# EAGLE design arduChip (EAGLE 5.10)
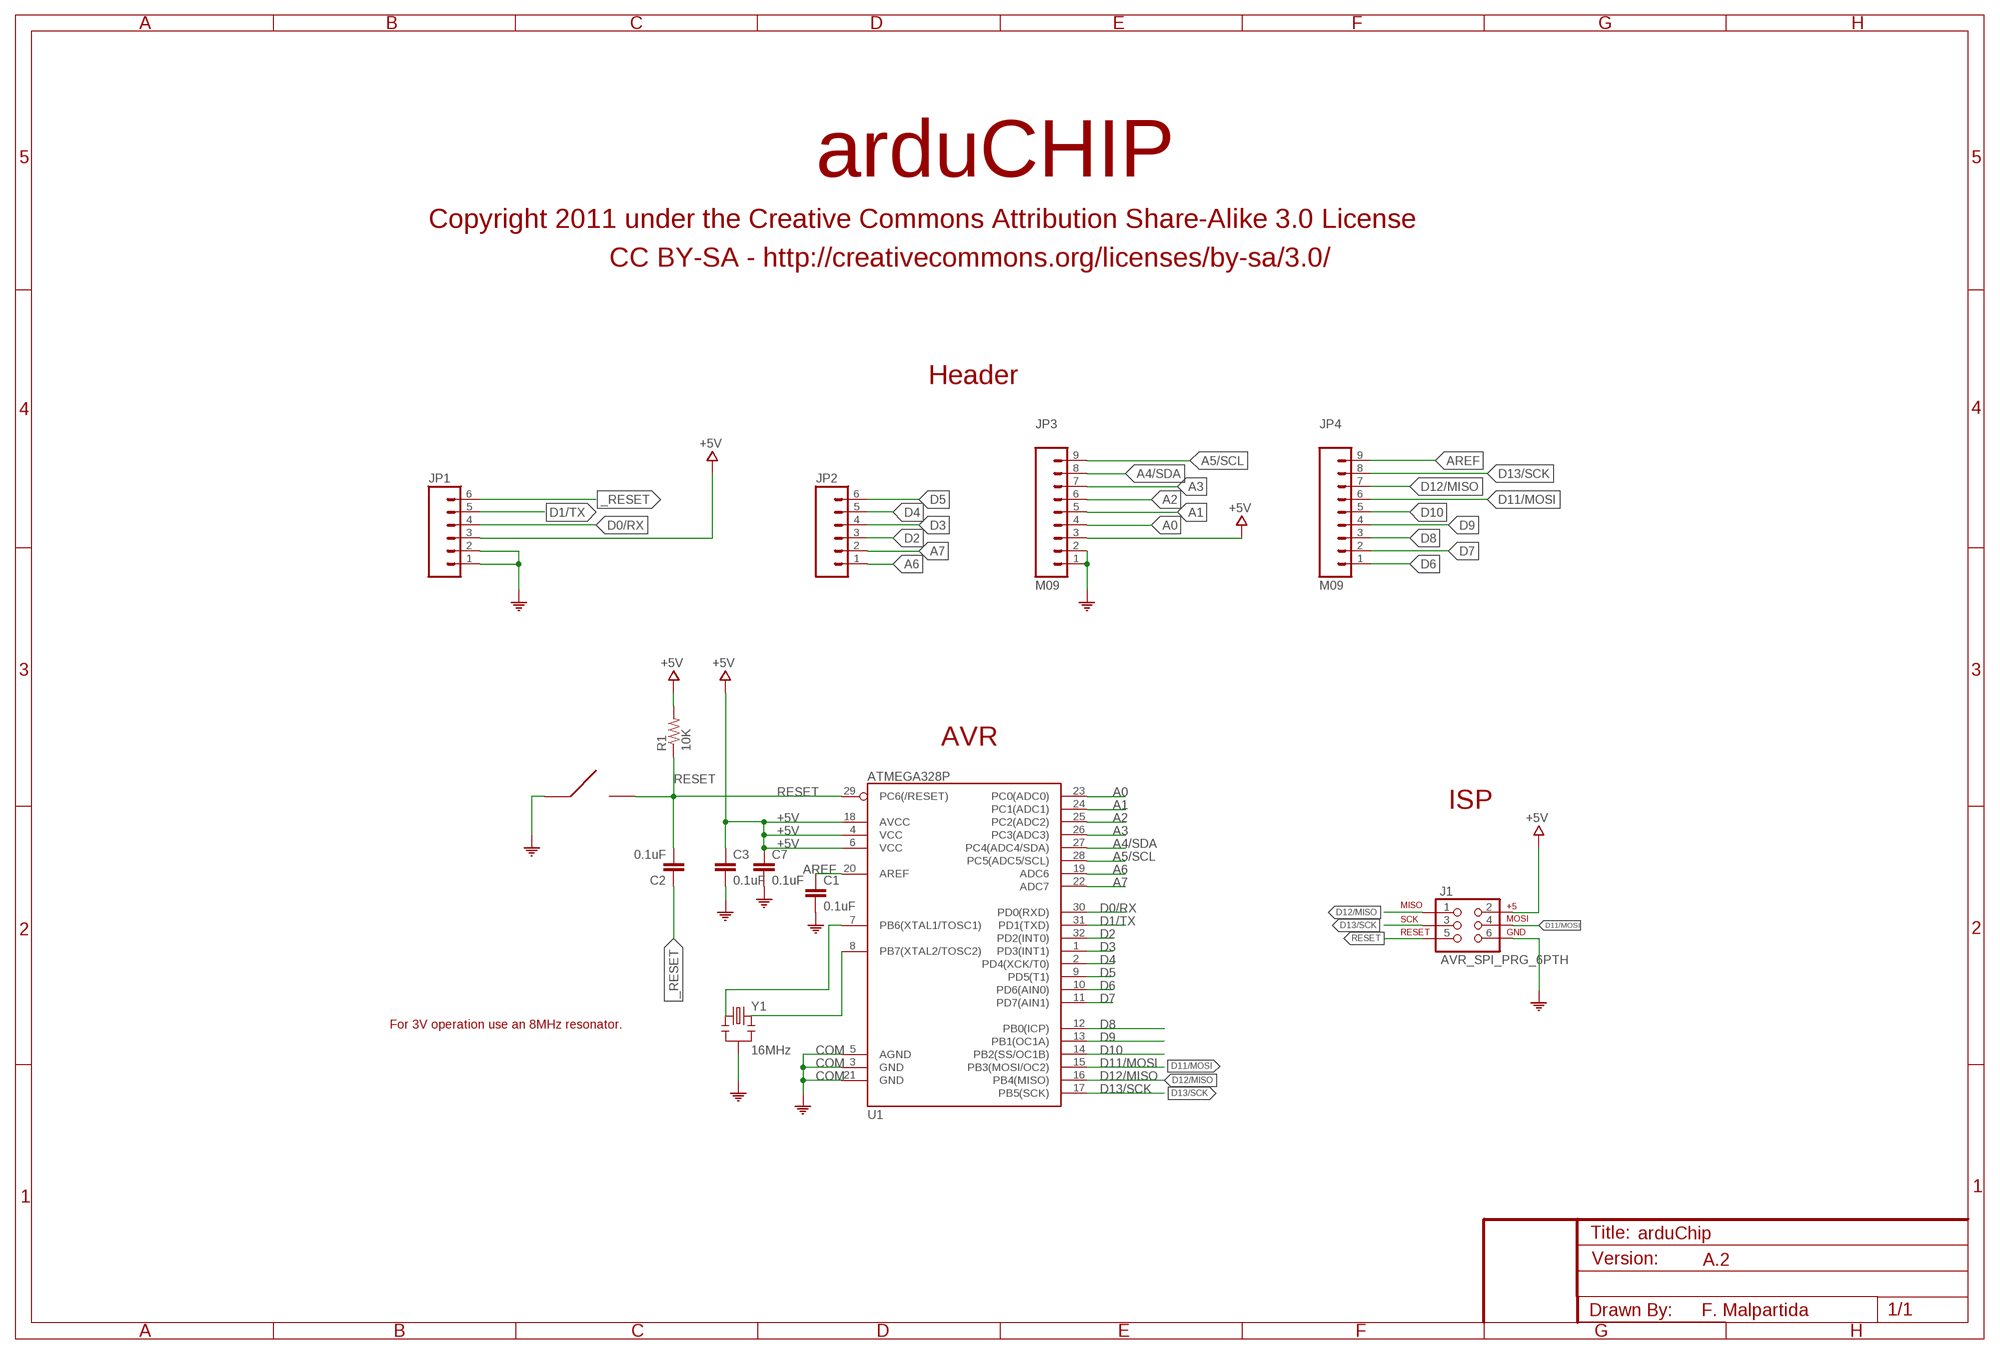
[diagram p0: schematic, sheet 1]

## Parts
C1  0.1uF  CAP0805  [0805]
C2  0.1uF  CAP0805  [0805]
C3  0.1uF  CAP0805  [0805]
C7  0.1uF  CAP0805  [0805]
J1  AVR_SPI_PRG_6PTH  [2X3]
JP1  M06SIP  [1X06]
JP2  M06SIP  [1X06]
JP3  M09  [1X09]
JP4  M09  [1X09]
R1  10K  RESISTOR0805-RES  [0805]
SW1  B3U-1000P  B3U-SWITCH_  [B3U_1000P]
U1  ATMEGA328P  ATMEGA168  [TQFP32-08]
Y1  16MHz  RESONATORSMD  [RESONATOR-SMD]

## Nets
+5V: C3.1 C7.1 J1.2 JP1.3 JP3.3 R1.2 U1.4(VCC) U1.6(VCC) U1.18(AVCC)
_RESET: C2.1 JP1.6
A0: JP3.4 U1.23(PC0(ADC0))
A1: JP3.5 U1.24(PC1(ADC1))
A2: JP3.6 U1.25(PC2(ADC2))
A3: JP3.7 U1.26(PC3(ADC3))
A4/SDA: JP3.8 U1.27(PC4(ADC4/SDA))
A5/SCL: JP3.9 U1.28(PC5(ADC5/SCL))
A6: JP2.1 U1.19(ADC6)
A7: JP2.2 U1.22(ADC7)
AREF: C1.1 JP4.9 U1.20(AREF)
COM: C1.2 C3.2 C7.2 J1.6 JP1.1 JP1.2 JP3.1 JP3.2 SW1.P$1 U1.3(GND) U1.5(AGND) U1.21(GND) Y1.2
D0/RX: JP1.4 U1.30(PD0(RXD))
D1/TX: JP1.5 U1.31(PD1(TXD))
D2: JP2.3 U1.32(PD2(INT0))
D3: JP2.4 U1.1(PD3(INT1))
D4: JP2.5 U1.2(PD4(XCK/T0))
D5: JP2.6 U1.9(PD5(T1))
D6: JP4.1 U1.10(PD6(AIN0))
D7: JP4.2 U1.11(PD7(AIN1))
D8: JP4.3 U1.12(PB0(ICP))
D9: JP4.4 U1.13(PB1(OC1A))
D10: JP4.5 U1.14(PB2(SS/OC1B))
D11/MOSI: J1.4 JP4.6 U1.15(PB3(MOSI/OC2))
D12/MISO: J1.1 JP4.7 U1.16(PB4(MISO))
D13/SCK: J1.3 JP4.8 U1.17(PB5(SCK))
N$1: U1.8(PB7(XTAL2/TOSC2)) Y1.3
N$2: U1.7(PB6(XTAL1/TOSC1)) Y1.1
RESET: C2.2 J1.5 R1.1 SW1.P$2 U1.29(PC6(/RESET))

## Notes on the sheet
- arduCHIP
- Copyright 2011 under the Creative Commons Attribution Share-Alike 3.0 License
- CC BY-SA - http://creativecommons.org/licenses/by-sa/3.0/
- Header
- AVR
- ISP
- For 3V operation use an 8MHz resonator.
- A.2
- F. Malpartida

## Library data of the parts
C1-C3 C7 = SparkFun:CAP: Capacitor
J1 = SparkFun:AVR_SPI_PRG_6: AVR ISP 6 Pin This is the reduced ISP connector for AVR programming. Common on Arduino. This footprint will take up less PCB space and can be used with a 10-pin to 6-pin adapter such as SKU: BOB-08508
JP1 JP2 = sparkfun_2:M06: Header 6 Standard 6-pin 0.1" header. Use with straight break away headers (SKU : PRT-00116), right angle break away headers (PRT-00553), swiss pins (PRT-00743), machine pins (PRT-00117), and female headers (PRT-00115). Molex polarized connector foot print use with SKU : PRT-08094 with associated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
JP3 JP4 = sparkfun_2:M09: Header 9 Standard 9-pin 0.1" header. Use with straight break away headers (SKU : PRT-00116), right angle break away headers (PRT-00553), swiss pins (PRT-00743), machine pins (PRT-00117), and female headers (PRT-00115).
R1 = SparkFun:RESISTOR: Resistor
SW1 = fmc:B3U-SWITCH
U1 = SparkFun:ATMEGA168
Y1 = SparkFun:RESONATOR: Resonator Small SMD resonator. This is the itty bitty 10/20MHz resonators with built in caps. CSTCE10M0G55 and CSTCE20M0V53. Footprint has been reviewed closely but hasn't been tested yet.

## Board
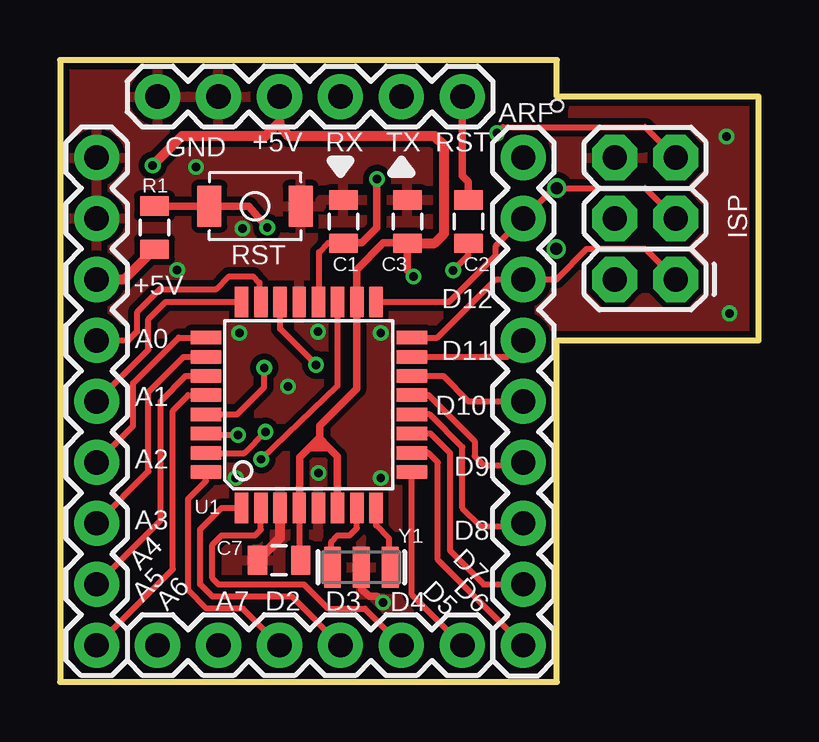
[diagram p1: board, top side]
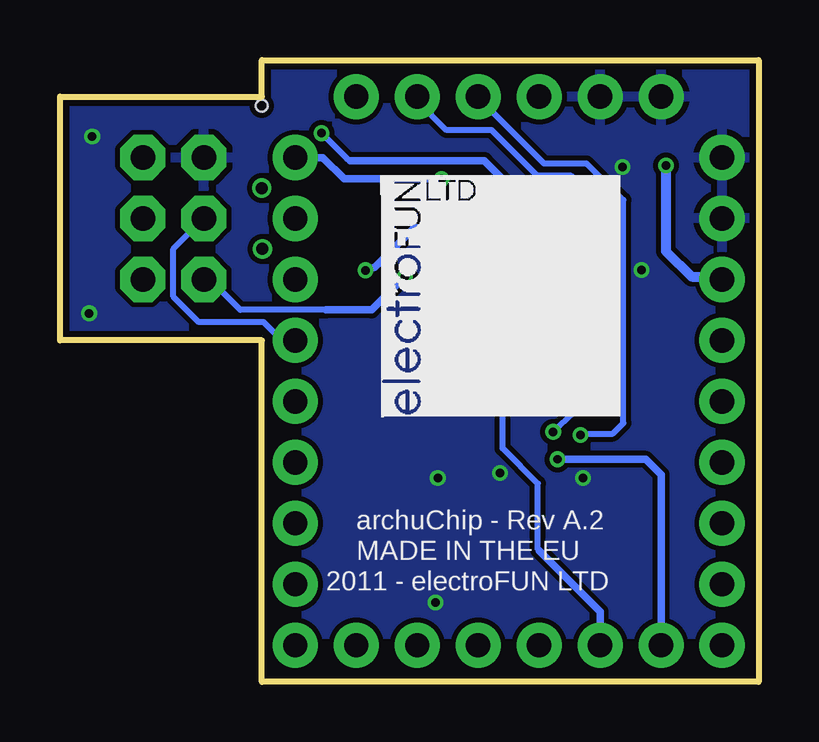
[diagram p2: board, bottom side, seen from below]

Size 29.11 x 25.91 mm. Coordinates in mm from the lower left corner, seen from the top.
Outline: 0,0 20.7,0 20.7,14.22 29.11,14.22 29.11,24.38 20.7,24.38 20.7,25.91 0,25.91 0,0
Copper layers (1*16): Top 0.0356mm / dielectric 1.5011mm / Bottom 0.0356mm
Design rules "SparkFun_itead_fmc *": minimum track width 8mil, minimum drill 0.35mm, track to track 8mil, track to pad 8mil, pad to pad 8mil, via to via 8mil, smd to smd 8mil, copper to edge 10mil, drill to drill 8mil, minimum pad ring 12mil, minimum via ring 6mil, stop-mask expansion 4mil, vias tented up to drill 25mil, thermal gap 10mil
Holes 0.5 mm at 20.7,24

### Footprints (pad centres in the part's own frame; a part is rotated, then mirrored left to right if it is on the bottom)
0805 = smd 0.8 x 1.2: 1 -0.9,0; 2 0.9,0
2X3 = drill 1.016 pad 1.88 octagon: 1 0,0; 2 0,2.54; 3 2.54,0; 4 2.54,2.54; 5 5.08,0; 6 5.08,2.54
1X06 = drill 1.016 pad 1.88 round: 1 0,0; 2 2.54,0; 3 5.08,0; 4 7.62,0; 5 10.16,0; 6 12.7,0
1X09 = drill 1.016 pad 1.88 round: 1 0,0; 2 2.54,0; 3 5.08,0; 4 7.62,0; 5 10.16,0; 6 12.7,0; 7 15.24,0; 8 17.78,0; 9 20.32,0
B3U_1000P = smd 1 x 1.7: P$1 -1.9,0; P$2 1.9,0
TQFP32-08 = smd 1.27 x 0.559: 1 -4.293,2.8; 2 -4.293,2; 3 -4.293,1.2; 4 -4.293,0.4; 5 -4.293,-0.4; 6 -4.293,-1.2; 7 -4.293,-2; 8 -4.293,-2.8; 17 4.293,-2.8; 18 4.293,-2; 19 4.293,-1.2; 20 4.293,-0.4; 21 4.293,0.4; 22 4.293,1.2; 23 4.293,2; 24 4.293,2.8 | smd 0.559 x 1.27: 9 -2.8,-4.293; 10 -2,-4.293; 11 -1.2,-4.293; 12 -0.4,-4.293; 13 0.4,-4.293; 14 1.2,-4.293; 15 2,-4.293; 16 2.8,-4.293; 25 2.8,4.293; 26 2,4.293; 27 1.2,4.293; 28 0.4,4.293; 29 -0.4,4.293; 30 -1.2,4.293; 31 -2,4.293; 32 -2.8,4.293
RESONATOR-SMD = smd 0.7 x 1.7: 1 -1.2,0; 2 0,0; 3 1.2,0

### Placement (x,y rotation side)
C1  11.81,19.18 90 top
C2  17.02,19.18 270 top
C3  14.48,19.18 90 top
C7  9.13,5.06 180 top
J1  25.65,16.76 90 top
JP1  4.06,24.38 0 top
JP2  4.06,1.52 0 top
JP3  1.52,21.84 270 top
JP4  19.3,1.52 90 top
R1  3.94,18.92 270 top
SW1  8.13,19.81 180 top
U1  10.37,11.54 90 top
U$36  [ELECTROFUN]  15.75,11.05 0 bottom
Y1  12.56,4.77 0 top

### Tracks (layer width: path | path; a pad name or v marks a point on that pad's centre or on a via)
+5V  (via drill 0.35, 0.35 pad 0.25)
  Top 0.254: U1.18 12.4,15.87 | 9.98,5.18 9.98,7.13 U1.4 | 11.56,7.26 U1.6 | JP1.3 9.14,23.32
  Top 0.305: 9.14,23.24 JP1.3 | 9.98,7.13 9.98,9.35 10.39,9.75 | 10.39,9.75 10.41,9.78 | 10.41,9.78 10.82,9.78 | 11.18,9.78 11.56,9.4 11.56,7.26 | C7.1 10.03,5.21 9.98,5.18 | 12.37,15.81 12.37,17.17 13.46,18.29 14.47,18.29 C3.1 14.48,17.14 v14.73,16.89 | U1.18 12.37,12.21 10.82,10.67 10.82,9.78 | 11.18,9.78 10.82,9.78 | 10.41,9.78 10.79,10.16 11.18,9.78 | 10.39,9.75 11.18,9.75 11.18,9.78
  Top 0.406: C3.1 15.61,18.28 16,18.67 16,22.35 15.62,22.73 9.52,22.73 9.14,23.24 | U1.18 12.37,15.81 | JP3.3 2.68,16.76 R1.2 | 9.14,23.32 8.56,22.73 5.08,22.73 v3.86,21.51
  Bottom 0.254: J1.2 22.86,16.76 21.59,15.49 18.03,15.49
  Bottom 0.305: v14.73,16.89 16.13,15.49 18.03,15.49
  Bottom 0.406: v3.86,21.51 3.86,17.95 2.79,16.88 1.7,16.88 JP3.3
_RESET
  Top 0.305: JP1.6 16.76,21.08 17.02,20.83 C2.1
A0
  Top 0.254: JP3.4 2.84,14.22 3.23,14.61 3.23,15.42 4.17,16.36 6.5,16.36 7.04,16.89 8.05,16.89 8.31,16.64 8.31,15.9 U1.23
A1
  Top 0.254: U1.24 4.4,15.83 3.68,15.11 3.68,13.84 JP3.5
A2
  Top 0.254: U1.25 4.94,14.34 3.05,12.45 3.05,10.67 JP3.6
A3
  Top 0.254: U1.26 5.16,13.54 3.68,12.06 3.68,8.76 JP3.7
A4/SDA
  Top 0.254: U1.27 5.25,12.74 4.19,11.68 4.19,6.73 JP3.8
A5/SCL
  Top 0.254: U1.28 5.34,11.94 4.7,11.3 4.7,4.7 JP3.9
A6  (via drill 0.35)
  Top 0.254: U1.19 11.57,12.33 v8.38,9.27
  Bottom 0.305: v8.38,9.27 4.7,9.27 4.06,8.64 JP2.1
A7  (via drill 0.35)
  Top 0.254: U1.22 9.17,14.71 v10.67,13.21
  Bottom 0.254: v10.67,13.21 10.67,9.73 9.19,8.26 9.19,5.51 9.14,5.46
  Bottom 0.305: 9.14,5.46 6.6,2.92 JP2.2
AREF  (via drill 0.35)
  Top 0.254: C1.1 11.16,18.28 10.79,17.91 10.79,15.86 U1.20
  Top 0.305: v13.21,20.95 13.21,18.92 12.57,18.29 11.82,18.29 C1.1
  Bottom 0.305: JP4.9 18.16,21.84 17.27,20.95 v13.21,20.95
COM  (via drill 0.35)
  Top 0.254: Y1.2 12.55,4.21
  Top 0.305: 12.55,4.21 12.57,4.19 12.57,3.86 12.88,3.56 13.21,3.56 v13.46,3.3
  Top 0.406: U1.3 9.17,6 C7.2
  other vias: 13.36,8.49 10.75,14.59 10.77,8.7 7.32,8.49 4.88,17.15 9.5,12.3 5.67,21.45 7.6,18.88 27.77,22.72 27.89,15.35 13.36,14.54 7.47,14.54
  pour Bottom: -0.76,26.92 30.99,26.92 30.99,-1.02 -0.76,-1.02
  pour Top (isolate 0.254): -0.97,26.92 30.78,26.92 30.78,-1.02 -0.76,-1.02
D0/RX  (via drill 0.35)
  Top 0.254: v7.42,10.29 6.13,10.29 U1.30
  Bottom 0.254: JP1.4 11.68,24.33 8.94,21.59 7.16,21.59 5.64,20.07 5.64,10.78 U1.30 7.36,10.34 v7.42,10.29
D1/TX  (via drill 0.35)
  Top 0.254: v8.56,10.41 7.67,9.53 6.09,9.53 U1.31
  Bottom 0.254: JP1.5 14.22,24.21 13,22.99 11.12,22.99 9.22,21.08 7.8,21.08 6.78,20.07 6.78,12.06 v8.56,10.41
D2
  Top 0.254: U1.32 6.07,8.36 5.33,7.62 5.33,3.81 6.1,3.05 7.62,3.05 JP2.3
D3
  Top 0.254: U1.1 6.74,7.25 5.84,6.35 5.84,4.06 6.35,3.56 9.65,3.56 JP2.4
  Bottom 0.203: JP2.4 11.68,1.27
D4
  Top 0.254: U1.2 8.37,6.34 8.13,6.1 6.73,6.1 6.35,5.71 6.35,4.32 6.6,4.06 10.16,4.06 11.18,3.05 12.7,3.05 JP2.5
D5
  Top 0.254: U1.9 14.66,3.63 JP2.6
D6
  Top 0.254: U1.10 15.35,9.54 15.75,9.14 15.75,5.08 JP4.1
D7
  Top 0.254: 14.48,10.41 14.55,10.34 U1.11 15.44,10.34 16.26,9.53 16.26,5.46 17.65,4.06 JP4.2
D8
  Top 0.254: U1.12 15.4,11.14 16.76,9.78 16.76,7.24 17.53,6.48 19.18,6.48 JP4.3
D9
  Top 0.254: U1.13 15.36,11.94 17.27,10.03 17.27,9.4 17.65,9.02 19.18,9.02 JP4.4
D10
  Top 0.254: U1.14 15.96,12.74 17.02,11.68 JP4.5
D11/MOSI
  Top 0.254: U1.15 18.62,13.54 JP4.6
  Bottom 0.254: JP4.6 19.86,14.22 20.62,14.99 23.32,14.99 24.38,16.05 24.38,18.03 J1.4
D12/MISO
  Top 0.254: U1.16 15.73,14.34 18.15,16.76 JP4.7 20.69,16.76 21.96,18.03 24.38,18.03 J1.1
D13/SCK  (via drill 0.5)
  Top 0.254: J1.3 24.38,20.57 v20.7,20.57 20.57,20.57 JP4.8 18.16,18.16 18.16,17.78 16.21,15.83 U1.17
N$1
  Top 0.254: U1.8 13.17,6.52 13.72,5.97 13.72,4.94 Y1.3
N$2
  Top 0.254: U1.7 12.37,6.4 12.06,6.1 11.56,6.1 11.3,5.84 11.3,4.82 Y1.1
N$3  (via drill 0.5)
  other vias: 20.68,18.03
RESET  (via drill 0.35)
  Top 0.254: C2.2 17.02,17.78 v16.38,17.14 | U1.29 7.38,11.14 8.51,12.27 v8.51,13.08 | v18.21,22.86 18.47,23.11 24.38,23.11 J1.5
  Top 0.305: R1.1 6.22,19.82 SW1.P$2 7.87,19.81 v8.64,18.92
  Bottom 0.254: 17.02,21.72 17.14,21.79 v18.21,22.86 | v8.64,18.92 8.64,13.21 v8.51,13.08
  Bottom 0.305: 17.02,21.72 11.43,21.72 v8.64,18.92 14.35,18.92 16,17.27 v16.38,17.14

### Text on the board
tPlace: ARF | GND | +5V | RX | TX | RST | ISP | RST | +5V | D12 | A0 | D11 | D10 | A1 | A2 | D9 | D8 | A3 | A4 | D7 | A5 | A6 | A7 | D2 | D3 | D4 | D5 | D6
bPlace: archuChip - Rev A.2 | MADE IN THE EU | 2011 - electroFUN LTD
